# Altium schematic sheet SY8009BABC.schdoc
size 127 x 101 mm
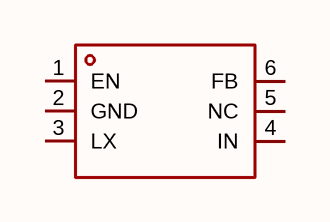
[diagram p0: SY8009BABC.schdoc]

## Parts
U?  sy8009babc  [SOT-23-6_L2.9-W1.6-P0.95-LS2.8-BR]  (value not drawn)

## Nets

Not connected (* = marked no-connect by the designer): U? 1(EN) 2(GND) 3(LX) 4(IN) 5(NC) 6(FB)

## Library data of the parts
U? = sy8009babc: 功能类型:降压型;工作电压:3V~5.5V;输出电压:-;输出电流:2A;输出类型:可调;; Manufacturer: Silergy(矽力杰); AddInBom: yes; ModelId: 18da8f6c14a34920b3e136b5c401a119; ModelName: SOT-23-6_L2.9-W1.6-H1.5-LS2.8-P0.95; ModelTransform: 110.73671,114.173,0,180,0,0,0.001,-0.003,0; Function: 降压型; Output Current: 2A; Frequency - Switching: 1MHz; Synchronous Rectifier: 是; Number of Outputs: 1; Topology: 降压式; Quiescent Current: 80uA; Switch tube (built-in/external): 内置; Output Type: 可调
